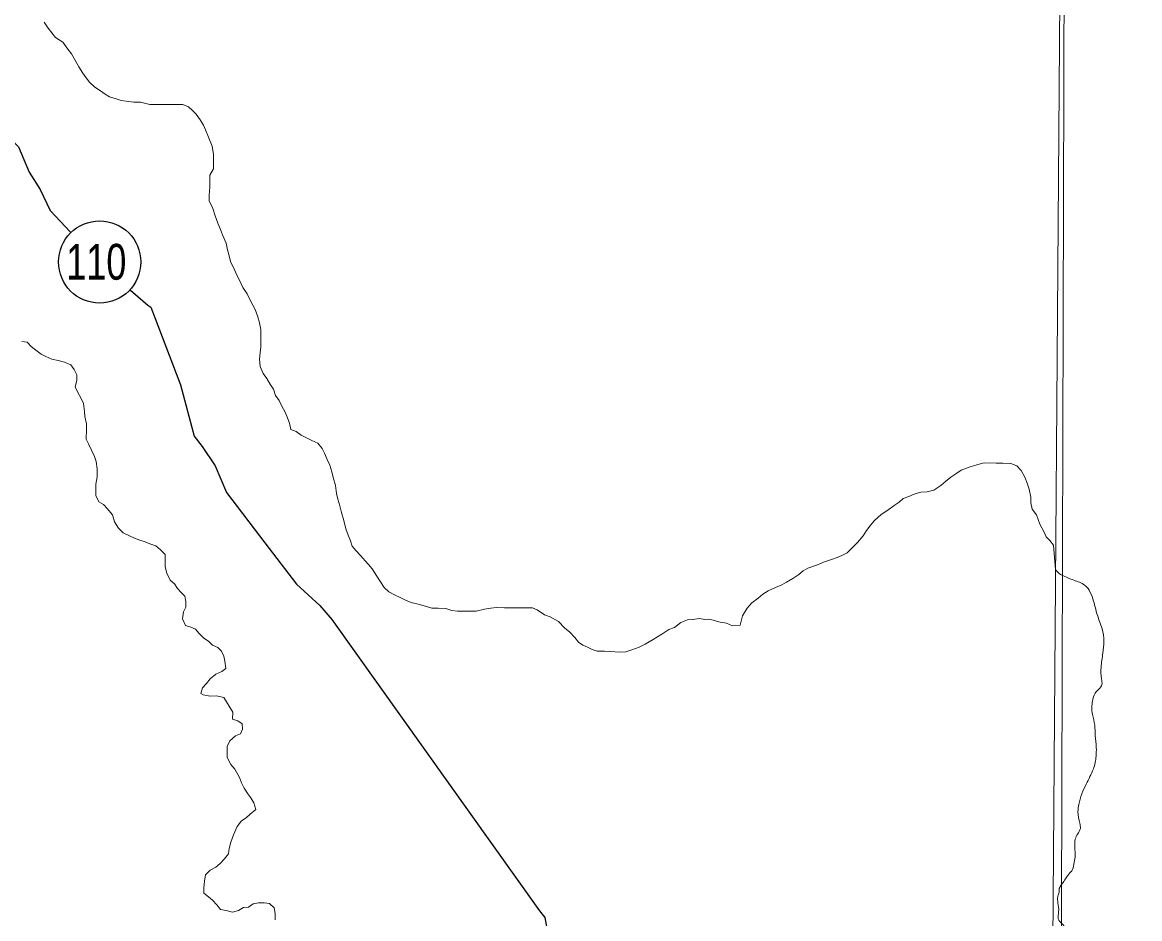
# Model space of a CAD drawing. Extents: x 553962 to 842807, y 8883888 to 9032388.
# Drawn here: x 616481 to 618663, y 8901080 to 8902830 of the extents above; entities that cross this region are included whole.
import ezdxf
from ezdxf.enums import TextEntityAlignment as Align

# ---------------------------------------------------------------- set-up
doc = ezdxf.new("R2010")
doc.units = 0
doc.header["$LTSCALE"] = 200
doc.layers.add('6', color=7, linetype='Continuous', lineweight=13)

msp = doc.modelspace()

# ---------------------------------------------------------------- linework, layer by layer
at = {"layer": '6'}
for points in [[(618663, 8924716.1), (618558.3, 8909803.7), (618456.5, 8896026.7)], [(616524, 8902830.2), (616532, 8902818.9), (616539.1, 8902809.7), (616546.1, 8902800.5), (616560.3, 8902791.2), (616570.4, 8902777.9), (616577.4, 8902768.7), (616582.5, 8902759.5), (616591.5, 8902743.1), (616599.6, 8902730.8), (616605.6, 8902721.6), (616612.7, 8902713.4), (616622.8, 8902703.2), (616633.9, 8902696), (616643, 8902689.8), (616651.3, 8902684.9), (616664.3, 8902680.5), (616674.5, 8902677.4), (616688.7, 8902675.3), (616698.9, 8902674.2), (616712.1, 8902674.1), (616730.4, 8902669.9), (616742.6, 8902669.8), (616754.8, 8902669.7), (616772.1, 8902669.6), (616784.3, 8902669.6), (616794.5, 8902669.5), (616805.6, 8902665.3), (616813.7, 8902658.2), (616820.8, 8902651), (616828.8, 8902639.7), (616834.9, 8902629.5), (616838.9, 8902620.3), (616844.9, 8902606), (616851.9, 8902588.6), (616854.8, 8902572.3), (616854.7, 8902555), (616854.6, 8902543.8), (616847.4, 8902531.6), (616847.3, 8902519.4), (616847.2, 8902508.2), (616846.1, 8902492.9), (616846.1, 8902481.7), (616853.1, 8902466.4), (616858.1, 8902452.1), (616863, 8902437.8), (616868, 8902425.5), (616872, 8902415.3), (616879.1, 8902399), (616882, 8902385.7), (616885, 8902374.5), (616888, 8902363.3), (616896, 8902345.9)], [(616896, 8902345.9), (616900, 8902336.7), (616905, 8902326.5), (616912, 8902312.2), (616920.1, 8902299.9), (616927.1, 8902286.6), (616936.1, 8902269.2), (616941.1, 8902254.9), (616944.1, 8902243.7), (616947.1, 8902230.4), (616947, 8902218.2), (616946.9, 8902207), (616946.8, 8902196.8), (616945.7, 8902184.6), (616944.6, 8902172.4), (616945.6, 8902158.1), (616951.6, 8902144.8), (616958.6, 8902134.6), (616965.7, 8902122.3), (616971.7, 8902114.1), (616975.7, 8902101.9), (616982.7, 8902091.7), (616988.8, 8902079.4), (616993.8, 8902070.2), (616997.8, 8902061), (617002.8, 8902047.7), (617005.7, 8902035.5), (617015.9, 8902031.3), (617026, 8902024.1), (617037.2, 8902018), (617046.3, 8902013.8), (617058.5, 8902008.7), (617066.5, 8901998.4), (617071.5, 8901989.2), (617076.5, 8901976.9), (617081.6, 8901965.7), (617085.5, 8901952.4)], [(616480.3, 8902206.8), (616490.5, 8902205.7), (616498.6, 8902197.5), (616507.7, 8902190.3), (616517.8, 8902182.1), (616526.9, 8902178), (616539.1, 8902172.8), (616551.3, 8902169.7), (616563.5, 8902166.5), (616575.7, 8902161.3), (616582.7, 8902152.1), (616587.7, 8902141.9), (616587.7, 8902130.7), (616584.5, 8902118.5), (616590.5, 8902106.2), (616595.6, 8902097)], [(616595.6, 8902097), (616600.6, 8902085.8), (616602.5, 8902070.5), (616603.4, 8902060.3), (616606.4, 8902046), (616606.3, 8902035.8), (616606.2, 8902016.5), (616610.2, 8902007.3), (616616.2, 8901995), (616622.2, 8901982.8), (616625.2, 8901972.6), (616627.2, 8901958.3), (616627.1, 8901943), (616624.9, 8901928.8), (616624.8, 8901917.6), (616624.8, 8901906.3), (616630.8, 8901894.1), (616639.9, 8901888.9), (616647, 8901880.7), (616657.1, 8901868.4), (616661, 8901855.2), (616669.1, 8901842.9), (616678.2, 8901833.7)], [(617882.8, 8901653.4), (617884.2, 8901658.2), (617887.4, 8901671.5), (617896.6, 8901686.7), (617905.8, 8901696.8), (617918.1, 8901705.9), (617927.3, 8901714), (617937.6, 8901720), (617951.8, 8901727.1), (617964.1, 8901732.1), (617973.3, 8901737.1), (617985.5, 8901744.2), (617997.8, 8901752.3), (618006, 8901759.3), (618015.2, 8901764.4), (618035.6, 8901771.4), (618045.8, 8901776.4), (618061.1, 8901781.4), (618072.3, 8901785.4), (618081.5, 8901789.4), (618091.7, 8901794.4), (618100.9, 8901803.6), (618112.2, 8901814.7), (618123.4, 8901827.9), (618129.6, 8901838), (618137.8, 8901849.2), (618145, 8901857.3), (618158.3, 8901869.4), (618171.6, 8901877.5), (618183.8, 8901886.6), (618193.1, 8901893.6), (618201.2, 8901900.7), (618212.5, 8901904.7), (618222.7, 8901908.7), (618235.9, 8901912.7), (618248.1, 8901913.7), (618261.4, 8901916.6), (618274.7, 8901925.7), (618283.9, 8901933.8), (618294.1, 8901941.9), (618304.3, 8901948.9), (618314.5, 8901956), (618329.8, 8901962), (618347.2, 8901967), (618359.4, 8901970), (618382.8, 8901969.8), (618396, 8901969.8), (618411.3, 8901968.6), (618423.4, 8901964.5), (618431.5, 8901955.3), (618438.5, 8901942), (618443.6, 8901930.7), (618447.5, 8901918.5), (618450.5, 8901903.2), (618450.4, 8901892), (618453.4, 8901879.7), (618461.4, 8901868.5), (618468.4, 8901850.1), (618476.5, 8901834.8), (618480.5, 8901825.6), (618487.5, 8901818.4), (618494.6, 8901809.2), (618499, 8901761.6)], [(617085.5, 8901952.4), (617088.5, 8901941.2), (617092.5, 8901925.9), (617094.4, 8901910.6), (617097.4, 8901899.4), (617101.3, 8901886.1), (617104.3, 8901872.9), (617109.3, 8901857.6), (617113.2, 8901841.2), (617117.2, 8901829), (617122.2, 8901817.7), (617125.2, 8901807.5), (617132.3, 8901799.3), (617141.4, 8901789.1), (617150.5, 8901778.8), (617157.5, 8901771.7), (617164.6, 8901763.5), (617173.7, 8901749.1), (617180.7, 8901737.9), (617187.7, 8901726.6), (617196.8, 8901718.4), (617208, 8901712.2), (617219.1, 8901707.1), (617229.3, 8901701.9), (617240.4, 8901697.8), (617256.7, 8901693.6), (617267.8, 8901690.5), (617281, 8901686.3), (617293.2, 8901686.2), (617308.5, 8901686.1), (617319.7, 8901682), (617330.8, 8901680.9), (617345.1, 8901680.8), (617355.3, 8901680.7), (617367.5, 8901680.7), (617383.8, 8901684.6), (617396, 8901686.6), (617407.2, 8901687.5), (617422.5, 8901687.4), (617437.7, 8901687.3), (617454, 8901687.2), (617464.2, 8901687.2), (617477.4, 8901687.1), (617486.5, 8901682.9), (617500.7, 8901673.7), (617511.8, 8901669.6), (617528.1, 8901660.3), (617540.2, 8901648), (617550.3, 8901639.8), (617560.4, 8901629.5), (617567.5, 8901620.3), (617575.6, 8901614.1), (617584.7, 8901610), (617593.8, 8901605.9), (617604, 8901602.7), (617618.2, 8901602.6), (617630.4, 8901601.6), (617646.7, 8901600.4), (617659.9, 8901601.4), (617671.1, 8901605.4), (617685.4, 8901610.4), (617697.6, 8901616.4), (617713, 8901625.5), (617730.3, 8901635.6), (617743.6, 8901644.6)], [(616678.2, 8901833.7), (616690.3, 8901827.5), (616700.5, 8901823.3), (616710.6, 8901819.2), (616720.8, 8901816.1), (616729.9, 8901811.9), (616742.1, 8901807.8), (616751.2, 8901800.6), (616760.3, 8901791.4), (616760.2, 8901780.2), (616760.1, 8901766.9), (616763.1, 8901754.7), (616770.1, 8901741.4), (616778.2, 8901734.2), (616784.2, 8901725), (616791.3, 8901716.8), (616798.4, 8901709.6), (616800.3, 8901699.4), (616800.3, 8901688.2), (616796.1, 8901679.1), (616794, 8901665.8), (616800, 8901652.6), (616810.2, 8901649.4), (616819.3, 8901645.3), (616826.4, 8901637.1), (616835.5, 8901627.9), (616844.6, 8901621.7), (616852.7, 8901614.5), (616862.8, 8901609.4), (616869.9, 8901602.2), (616874.9, 8901593), (616876.8, 8901582.8), (616878.8, 8901568.5), (616870.6, 8901562.5), (616859.4, 8901557.4), (616848.1, 8901548.3), (616840.9, 8901539.2), (616832.8, 8901531.1), (616829.6, 8901519.9), (616834.3, 8901517)], [(617743.6, 8901644.6), (617754.8, 8901648.6), (617767.1, 8901658.7), (617779.9, 8901663.6), (617790.1, 8901664.4), (617803.5, 8901666), (617813.7, 8901664.4), (617818.3, 8901665.2), (617827.8, 8901663.6), (617844.2, 8901658.9), (617856, 8901657.3), (617867.8, 8901651.8), (617882.8, 8901653.4)], [(616834.3, 8901517), (616847.9, 8901514.7), (616860.7, 8901515), (616874.9, 8901511.8), (616892, 8901483.2), (616891.9, 8901470), (616902.1, 8901466.8), (616910.2, 8901460.7), (616911.1, 8901450.5), (616907, 8901441.3), (616897.8, 8901437.3), (616886.6, 8901427.2), (616881.4, 8901416.1), (616881.3, 8901405.9), (616881.2, 8901394.7), (616888.3, 8901381.4), (616896.3, 8901372.1), (616905.4, 8901355.8), (616909.4, 8901345.6), (616914.4, 8901335.3), (616921.5, 8901324.1), (616927.5, 8901315.9), (616933.5, 8901306.7), (616937.5, 8901293.4), (616926.3, 8901284.3), (616918.1, 8901277.3), (616908.9, 8901271.2), (616900.7, 8901260.1), (616893.4, 8901243.8), (616888.2, 8901229.6), (616885.1, 8901217.4), (616884, 8901207.2), (616875.8, 8901197.1), (616867.6, 8901187.9), (616859.4, 8901180.8), (616848.2, 8901174.8), (616839, 8901165.7), (616836.9, 8901153.5), (616835.8, 8901140.2), (616835.7, 8901130.1), (616844.8, 8901122.9), (616852.9, 8901116.7), (616861, 8901107.5), (616868, 8901098.3), (616879.2, 8901096.2), (616891.4, 8901093), (616903.6, 8901096), (616912.8, 8901102.1), (616923, 8901103), (616932.2, 8901109.1), (616942.4, 8901111), (616953.6, 8901111), (616963.7, 8901109.9), (616972.8, 8901101.7), (616974.8, 8901090.5), (616974.7, 8901078.2)]]:
    msp.add_lwpolyline(points, dxfattribs=at)
msp.add_lwpolyline([(618535.2, 8909853.3), (607574.3, 8909890.7), (607543.3, 8898835.3), (618504.2, 8898795.8)], close=True, dxfattribs=at)
at = {"layer": '6', "lineweight": 25}
for points in [[(616044.3, 8903031.2), (616338.7, 8902741.3), (616398.6, 8902682.1), (616445.2, 8902616.8), (616473.6, 8902587.2), (616494.9, 8902537.3), (616516.1, 8902503.6), (616535.3, 8902462.8), (616575.3, 8902420.1)], [(616692.6, 8902307.3), (616726.2, 8902278.1), (616732.3, 8902274), (616740.4, 8902251.6), (616789.8, 8902122.1), (616817, 8902022.2), (616832.2, 8902001.8)], [(616832.2, 8902001.8), (616857.5, 8901964), (616879.7, 8901912), (616954.8, 8901814.1), (617016.6, 8901733.5), (617062.3, 8901691.6), (617085.6, 8901664.1), (617491.1, 8901095.8), (617501.2, 8901082.6), (617505.2, 8901061.2), (617519.8, 8900868.6), (617561, 8900712.6), (617580, 8900602.6), (617583.9, 8900553.7), (617583.7, 8900508.8), (617579.5, 8900483.4), (617569.1, 8900420.2), (617561.6, 8900327.5), (617544.5, 8899823.2), (617553.6, 8899807.9), (617563.8, 8899799.8), (617571, 8899793.8)]]:
    msp.add_lwpolyline(points, dxfattribs=at)
msp.add_circle((616632.2, 8902362.2), 80.3, dxfattribs=at)
at = {"layer": '6'}
msp.add_spline([(618499, 8901761.6), (618503.2, 8901756.5), (618514.3, 8901749.3), (618537.3, 8901740.1), (618557.5, 8901729.9), (618566, 8901718.5), (618573.2, 8901700), (618580, 8901674.2), (618589.5, 8901646.4), (618593.3, 8901621.8), (618591.2, 8901598.9), (618587.7, 8901571.1), (618588.4, 8901548.8), (618589.1, 8901537), (618583.5, 8901528.6), (618575.9, 8901520.3), (618571, 8901505), (618569.5, 8901492.9), (618571.1, 8901478.9), (618575.3, 8901458.1), (618576.3, 8901438.2), (618578.3, 8901414.3), (618577.9, 8901397.7), (618572.6, 8901372.7), (618558.5, 8901343), (618550.3, 8901324.2), (618544.1, 8901303.3), (618542.6, 8901289.4), (618545.9, 8901266.5), (618547.2, 8901256.2), (618542, 8901245.6), (618537.3, 8901235.3), (618536.4, 8901218.2), (618537.1, 8901203.9), (618535, 8901190.1), (618531.9, 8901176.4), (618524.9, 8901167.3), (618516, 8901155.2), (618510.6, 8901147.1), (618506.1, 8901139.1), (618505.3, 8901129.8), (618503, 8901122.9), (618503.4, 8901111.4), (618504.7, 8901093.6), (618504.2, 8901080), (618511.5, 8901070.3), (618519.3, 8901061), (618531.9, 8901048.2), (618539.3, 8901039.7), (618544.9, 8901022.6), (618545.9, 8901009.7), (618545.5, 8901001.1), (618542, 8900989.9), (618540.8, 8900979.8), (618540.4, 8900969.7)], degree=3, dxfattribs=at)

# ---------------------------------------------------------------- texts
at = {"layer": '6', "width": 0.75}
msp.add_text('110', height=70, dxfattribs=at).set_placement((616625.8, 8902327.6), align=Align.CENTER)

doc.saveas('drawing.dxf')
